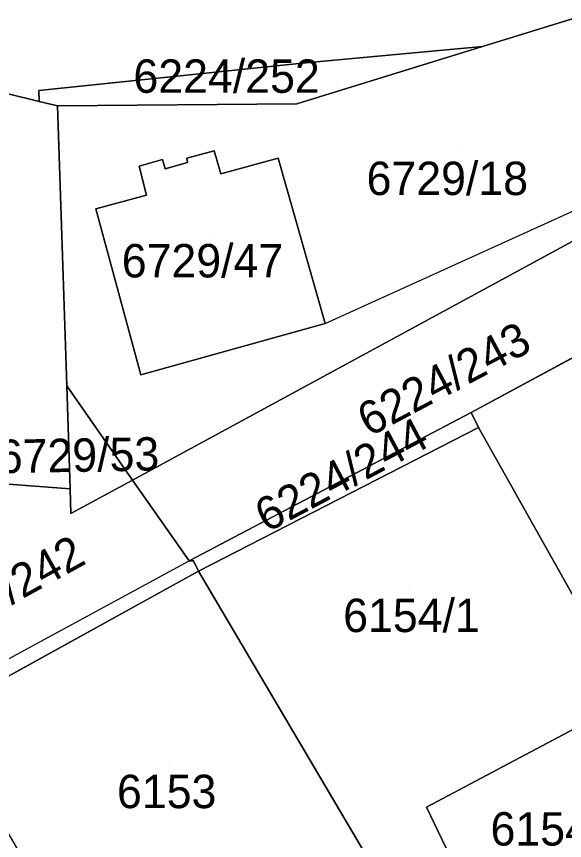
# Model space of a CAD drawing. Extents: x -266199 to -261993, y -1239047 to -1235108.
# Drawn here: x -263971.87 to -263939.05, y -1236358.81 to -1236309.48 of the extents above; entities that cross this region are included whole.
import ezdxf

# ---------------------------------------------------------------- set-up
doc = ezdxf.new("R2010")
doc.units = 0
for name, color, linetype in [('body_kn', 7, 'Continuous'), ('kladpar_druhypozemkov', 7, 'Continuous'), ('kladpar_hranice', 7, 'Continuous'), ('kladpar_parcelnecisla', 7, 'Continuous'), ('kladpar_plochy', 7, 'Continuous'), ('zappar_hrandruhpozemk', 7, 'Continuous')]:
    doc.layers.add(name, color=color, linetype=linetype)

msp = doc.modelspace()

# ---------------------------------------------------------------- linework, layer by layer
at = {"layer": 'body_kn'}
for p, q in [((-263943.97, -1236311.27), (-263943.97, -1236311.27)), ((-263943.97, -1236311.27), (-263943.97, -1236311.27)), ((-263954.76, -1236312.28), (-263954.76, -1236312.28)), ((-263970.53, -1236313.91), (-263970.53, -1236313.91)), ((-263970.53, -1236313.91), (-263970.53, -1236313.91)), ((-263970.5, -1236314.57), (-263970.5, -1236314.57)), ((-263969.42, -1236314.83), (-263969.42, -1236314.83)), ((-263969.42, -1236314.83), (-263969.42, -1236314.83)), ((-263955.08, -1236314.7), (-263955.08, -1236314.7)), ((-263960.03, -1236317.53), (-263960.03, -1236317.53)), ((-263963.13, -1236318.04), (-263963.13, -1236318.04)), ((-263961.67, -1236317.97), (-263961.67, -1236317.97)), ((-263956.2, -1236317.96), (-263956.2, -1236317.96)), ((-263964.53, -1236318.45), (-263964.53, -1236318.45)), ((-263961.63, -1236318.22), (-263961.63, -1236318.22)), ((-263962.97, -1236318.59), (-263962.97, -1236318.59)), ((-263959.63, -1236318.9), (-263959.63, -1236318.9)), ((-263964.08, -1236320.18), (-263964.08, -1236320.18)), ((-263967.11, -1236321), (-263967.11, -1236321)), ((-263953.38, -1236327.85), (-263953.38, -1236327.85)), ((-263964.42, -1236330.94), (-263964.42, -1236330.94)), ((-263964.42, -1236330.94), (-263964.42, -1236330.94)), ((-263968.86, -1236331.59), (-263968.86, -1236331.59)), ((-263968.86, -1236331.59), (-263968.86, -1236331.59)), ((-263944.65, -1236333.18), (-263944.65, -1236333.18)), ((-263944.21, -1236334.09), (-263944.21, -1236334.09)), ((-263964.92, -1236337.23), (-263964.92, -1236337.23)), ((-263964.92, -1236337.23), (-263964.92, -1236337.23)), ((-263968.66, -1236337.76), (-263968.66, -1236337.76)), ((-263968.61, -1236339.23), (-263968.61, -1236339.23)), ((-263961.53, -1236342.07), (-263961.53, -1236342.07)), ((-263961.53, -1236342.07), (-263961.53, -1236342.07)), ((-263961.27, -1236342.07), (-263961.27, -1236342.07)), ((-263960.97, -1236342.68), (-263960.97, -1236342.68)), ((-263947.32, -1236356.82), (-263947.32, -1236356.82))]:
    msp.add_line(p, q, dxfattribs=at)
at = {"layer": 'kladpar_druhypozemkov'}
for p, q in [((-263952.64, -1236313.42), (-263952.64, -1236313.42)), ((-263945.28, -1236317.48), (-263945.28, -1236317.48)), ((-263960.06, -1236322.5), (-263960.06, -1236322.5)), ((-263945.31, -1236330.26), (-263945.31, -1236330.26)), ((-263967.9, -1236334.5), (-263967.9, -1236334.5)), ((-263957.17, -1236340.25), (-263957.17, -1236340.25)), ((-263948.33, -1236343.73), (-263948.33, -1236343.73)), ((-263962.7, -1236354.27), (-263962.7, -1236354.27))]:
    msp.add_line(p, q, dxfattribs=at)
at = {"layer": 'kladpar_hranice'}
for points in [[(-263938.14, -1236309.48), (-263943.97, -1236311.27), (-263954.76, -1236312.28), (-263970.53, -1236313.91), (-263970.5, -1236314.57), (-263972.53, -1236314.07)], [(-263943.97, -1236311.27), (-263938.14, -1236309.48), (-263932.88, -1236318.56)], [(-263969.42, -1236314.83), (-263968.86, -1236331.59), (-263968.66, -1236337.76), (-263977.09, -1236337.11), (-263977.12, -1236336.48), (-263989.99, -1236335.39), (-263989.18, -1236328.96), (-263986.22, -1236329.42), (-263975.02, -1236331.17), (-263973.31, -1236320.99), (-263984.55, -1236319.15), (-263984.67, -1236319.92), (-263987.98, -1236319.39), (-263987.06, -1236312.13), (-263987, -1236311.01), (-263985.72, -1236311.36), (-263983.43, -1236311.98), (-263979.01, -1236313.27), (-263977.42, -1236313.65), (-263975.64, -1236313.93), (-263973.48, -1236314.1), (-263972.53, -1236314.07), (-263970.5, -1236314.57), (-263969.42, -1236314.83)], [(-263970.53, -1236313.91), (-263954.76, -1236312.28), (-263943.97, -1236311.27)], [(-263969.42, -1236314.83), (-263955.08, -1236314.7), (-263943.97, -1236311.27)], [(-263943.97, -1236311.27), (-263955.08, -1236314.7), (-263969.42, -1236314.83)], [(-263969.42, -1236314.83), (-263970.5, -1236314.57), (-263970.53, -1236313.91)], [(-263964.92, -1236337.23), (-263968.86, -1236331.59), (-263969.42, -1236314.83)], [(-263964.42, -1236330.94), (-263967.11, -1236321), (-263964.08, -1236320.18), (-263964.53, -1236318.45), (-263963.13, -1236318.04), (-263962.97, -1236318.59), (-263961.63, -1236318.22), (-263961.67, -1236317.97), (-263960.03, -1236317.53), (-263959.63, -1236318.9), (-263956.2, -1236317.96), (-263953.38, -1236327.85), (-263964.42, -1236330.94)], [(-263953.38, -1236327.85), (-263956.2, -1236317.96), (-263959.63, -1236318.9), (-263960.03, -1236317.53), (-263961.67, -1236317.97), (-263961.63, -1236318.22), (-263962.97, -1236318.59), (-263963.13, -1236318.04), (-263964.53, -1236318.45), (-263964.08, -1236320.18), (-263967.11, -1236321), (-263964.42, -1236330.94), (-263953.38, -1236327.85), (-263932.88, -1236318.56)], [(-263964.92, -1236337.23), (-263933.23, -1236320.04), (-263932.88, -1236318.56)], [(-263932.88, -1236318.56), (-263929.23, -1236324.87), (-263944.65, -1236333.18), (-263961.53, -1236342.07), (-263964.92, -1236337.23)], [(-263932.88, -1236318.56), (-263933.23, -1236320.04), (-263964.92, -1236337.23)], [(-263911.78, -1236355.63), (-263927.69, -1236363.44), (-263944.21, -1236334.09), (-263944.65, -1236333.18), (-263929.23, -1236324.87), (-263911.78, -1236355.63)], [(-263968.86, -1236331.59), (-263964.92, -1236337.23), (-263968.61, -1236339.23), (-263968.66, -1236337.76), (-263968.86, -1236331.59)], [(-263961.53, -1236342.07), (-263944.65, -1236333.18), (-263944.21, -1236334.09), (-263960.97, -1236342.68), (-263961.27, -1236342.07), (-263961.53, -1236342.07)], [(-263927.69, -1236363.44), (-263926.99, -1236364.91), (-263942.58, -1236373.84), (-263960.97, -1236342.68), (-263944.21, -1236334.09), (-263927.69, -1236363.44)], [(-263991.62, -1236348.24), (-263989.99, -1236335.39), (-263977.12, -1236336.48), (-263977.09, -1236337.11), (-263968.66, -1236337.76), (-263968.61, -1236339.23), (-263964.92, -1236337.23), (-263961.53, -1236342.07), (-263961.27, -1236342.07), (-263960.97, -1236342.68), (-263976.51, -1236351.26)], [(-263942.58, -1236373.84), (-263958.44, -1236382.24), (-263976.51, -1236351.26), (-263960.97, -1236342.68), (-263942.58, -1236373.84)], [(-263930.92, -1236361.61), (-263936.47, -1236351.07), (-263947.32, -1236356.82), (-263944.31, -1236363.09), (-263942.84, -1236362.43), (-263940.7, -1236366.58), (-263930.92, -1236361.61)], [(-263936.47, -1236351.07), (-263930.92, -1236361.61), (-263940.7, -1236366.58), (-263942.84, -1236362.43), (-263944.31, -1236363.09), (-263947.32, -1236356.82), (-263936.47, -1236351.07)]]:
    msp.add_lwpolyline(points, dxfattribs=at)
at = {"layer": 'kladpar_plochy'}
for p, q in [((-263943.97, -1236311.27), (-263938.14, -1236309.48)), ((-263938.14, -1236309.48), (-263943.97, -1236311.27)), ((-263955.08, -1236314.7), (-263943.97, -1236311.27)), ((-263943.97, -1236311.27), (-263954.76, -1236312.28)), ((-263954.76, -1236312.28), (-263970.53, -1236313.91)), ((-263970.5, -1236314.57), (-263972.53, -1236314.07)), ((-263970.53, -1236313.91), (-263970.5, -1236314.57)), ((-263969.42, -1236314.83), (-263955.08, -1236314.7)), ((-263968.86, -1236331.59), (-263969.42, -1236314.83)), ((-263960.03, -1236317.53), (-263961.67, -1236317.97)), ((-263959.63, -1236318.9), (-263960.03, -1236317.53)), ((-263963.13, -1236318.04), (-263964.53, -1236318.45)), ((-263962.97, -1236318.59), (-263963.13, -1236318.04)), ((-263961.67, -1236317.97), (-263961.63, -1236318.22)), ((-263956.2, -1236317.96), (-263959.63, -1236318.9)), ((-263953.38, -1236327.85), (-263956.2, -1236317.96)), ((-263964.53, -1236318.45), (-263964.08, -1236320.18)), ((-263961.63, -1236318.22), (-263962.97, -1236318.59)), ((-263964.08, -1236320.18), (-263967.11, -1236321)), ((-263933.23, -1236320.04), (-263964.92, -1236337.23)), ((-263967.11, -1236321), (-263964.42, -1236330.94)), ((-263944.65, -1236333.18), (-263929.23, -1236324.87)), ((-263964.42, -1236330.94), (-263953.38, -1236327.85)), ((-263964.92, -1236337.23), (-263968.86, -1236331.59)), ((-263944.21, -1236334.09), (-263944.65, -1236333.18)), ((-263960.97, -1236342.68), (-263944.21, -1236334.09)), ((-263944.21, -1236334.09), (-263927.69, -1236363.44)), ((-263927.69, -1236363.44), (-263944.21, -1236334.09)), ((-263977.09, -1236337.11), (-263968.66, -1236337.76)), ((-263968.61, -1236339.23), (-263964.92, -1236337.23)), ((-263964.92, -1236337.23), (-263961.53, -1236342.07)), ((-263968.66, -1236337.76), (-263968.61, -1236339.23)), ((-263961.53, -1236342.07), (-263961.27, -1236342.07)), ((-263961.27, -1236342.07), (-263960.97, -1236342.68)), ((-263976.51, -1236351.26), (-263960.97, -1236342.68)), ((-263960.97, -1236342.68), (-263976.51, -1236351.26)), ((-263960.97, -1236342.68), (-263942.58, -1236373.84)), ((-263942.58, -1236373.84), (-263960.97, -1236342.68)), ((-263936.47, -1236351.07), (-263947.32, -1236356.82)), ((-263947.32, -1236356.82), (-263944.31, -1236363.09))]:
    msp.add_line(p, q, dxfattribs=at)
for points in [[(-263969.42, -1236314.83), (-263968.86, -1236331.59), (-263968.66, -1236337.76), (-263977.09, -1236337.11), (-263977.12, -1236336.48), (-263989.99, -1236335.39), (-263989.18, -1236328.96), (-263986.22, -1236329.42), (-263975.02, -1236331.17), (-263973.31, -1236320.99), (-263984.55, -1236319.15), (-263984.67, -1236319.92), (-263987.98, -1236319.39), (-263987.06, -1236312.13), (-263987, -1236311.01), (-263985.72, -1236311.36), (-263983.43, -1236311.98), (-263979.01, -1236313.27), (-263977.42, -1236313.65), (-263975.64, -1236313.93), (-263973.48, -1236314.1), (-263972.53, -1236314.07), (-263970.5, -1236314.57)], [(-263970.53, -1236313.91), (-263954.76, -1236312.28), (-263943.97, -1236311.27), (-263955.08, -1236314.7), (-263969.42, -1236314.83), (-263970.5, -1236314.57)], [(-263964.42, -1236330.94), (-263967.11, -1236321), (-263964.08, -1236320.18), (-263964.53, -1236318.45), (-263963.13, -1236318.04), (-263962.97, -1236318.59), (-263961.63, -1236318.22), (-263961.67, -1236317.97), (-263960.03, -1236317.53), (-263959.63, -1236318.9), (-263956.2, -1236317.96), (-263953.38, -1236327.85)], [(-263964.92, -1236337.23), (-263933.23, -1236320.04), (-263932.88, -1236318.56), (-263929.23, -1236324.87), (-263944.65, -1236333.18), (-263961.53, -1236342.07)], [(-263968.86, -1236331.59), (-263964.92, -1236337.23), (-263968.61, -1236339.23), (-263968.66, -1236337.76)], [(-263961.53, -1236342.07), (-263944.65, -1236333.18), (-263944.21, -1236334.09), (-263960.97, -1236342.68), (-263961.27, -1236342.07)], [(-263936.47, -1236351.07), (-263930.92, -1236361.61), (-263940.7, -1236366.58), (-263942.84, -1236362.43), (-263944.31, -1236363.09), (-263947.32, -1236356.82)]]:
    msp.add_lwpolyline(points, close=True, dxfattribs=at)
at = {"layer": 'zappar_hrandruhpozemk'}
msp.add_line((-263976.98, -1236350.45), (-263961.53, -1236342.07), dxfattribs=at)

# ---------------------------------------------------------------- texts
at = {"layer": 'kladpar_parcelnecisla'}
for s, p in [('6224/252', (-263964.864, -1236314.05)), ('6729/18', (-263950.904, -1236320.17)), ('6729/47', (-263965.563, -1236325.1)), ('6154/1', (-263952.306, -1236346.33)), ('6153', (-263965.848, -1236356.87)), ('6154/2', (-263943.482, -1236359.11))]:
    msp.add_text(s, height=2, dxfattribs=at).set_placement(p)
for s, rotation, p in [('6224/243', 28, (-263950.745, -1236334.671)), ('6224/244', 28, (-263956.884, -1236340.403)), ('6729/53', 1, (-263972.969, -1236336.822)), ('6224/242', 29, (-263977.359, -1236347.6))]:
    msp.add_text(s, height=2, rotation=rotation, dxfattribs=at).set_placement(p)

doc.saveas('drawing.dxf')
